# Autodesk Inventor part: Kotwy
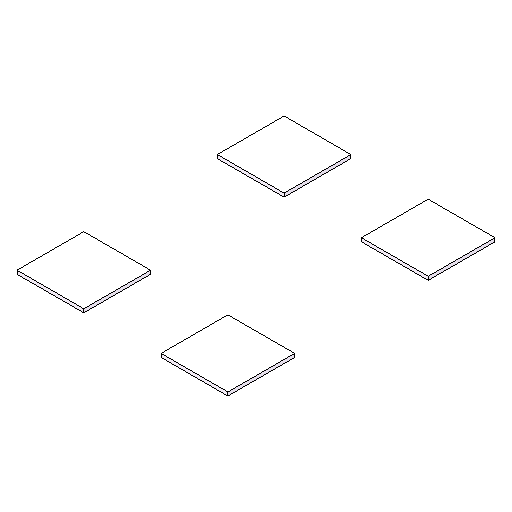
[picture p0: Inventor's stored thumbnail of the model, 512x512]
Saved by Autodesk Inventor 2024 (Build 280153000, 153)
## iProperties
Company: ATC
Created: 2023-03
Part Number: Kotwy
Document SubType Name: Modeling
Designer: Andrzej Jaskulski
Density: 1 g/cm^3
Mass: 180.5 g
Surface Area: 798 cm^2
Volume: 180.5 cm^3
Material: Kurs-AJ
Appearance: Kurs-AJ
Checked By: A.J.
Engr Approved By: Andrzej Jaskulski
Mfg Approved By: Andrzej Jaskulski
Authority: A.J.
Title: A.J.: Kurs R2024-MEP
Author: Andrzej Jaskulski
Revision Number: 1/24
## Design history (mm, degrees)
sketch "Szkic1"
  geometry: L1 (-30, 30)-(65, 30); L2 (65, 30)-(65, -65); L3 (65, -65)-(-30, -65); L4 (-30, -65)-(-30, 30); L5 (-30, -350)-(65, -350); L6 (65, -350)-(65, -255); L7 (65, -255)-(-30, -255); L8 (-30, -255)-(-30, -350); L9 (175, -350)-(270, -350); L10 (270, -350)-(270, -255); L11 (270, -255)-(175, -255); L12 (175, -255)-(175, -350); L13 (175, -65)-(270, -65); L14 (270, -65)-(270, 30); L15 (270, 30)-(175, 30); L16 (175, 30)-(175, -65); 5 further points
  constraints: 32 end point, 8 parallel, 7 perpendicular, 4 horizontal, 5 other
  dimensions: "d0" = 30 distance from line of L1 point (0, 0) (= X); "d1" = 30 distance from line of L4 point (0, 0) (= X); "d3" = 30 distance from line of point (35, -35) L2 (= X); "d4" = 30 distance from line of point (35, -35) L3 (= X); "Y" = 95 distance of L1.end L2.end (derived); "d7" = 30 distance from line of point (0, -320) L5 (= X); "d8" = 30 distance from line of point (0, -320) L8 (= X); "d9" = 95 distance of L5.start L5.end (= Y); "d10" = 30 distance from line of point (240, -320) L9 (= X); "d11" = 30 distance from line of point (240, -320) L10 (= X); "d12" = 95 distance of L9.start L9.end (= Y); "d13" = 30 distance from line of point (240, 0) L14 (= X); "d14" = 30 distance from line of point (240, 0) L15 (= X); "d15" = 95 distance of L14.end L15.end (= Y)
extrude "Wyciągnięcie proste1" new body sketch "Szkic1" distance "d16" = 5; taper "d17" = 0 deg
node "Bryła1"
node "Korpusy bryłowe"
node "Korpusy powierzchniowe"
other parameters: "X" = 30 [user parameter; used in 10 equation terms]
